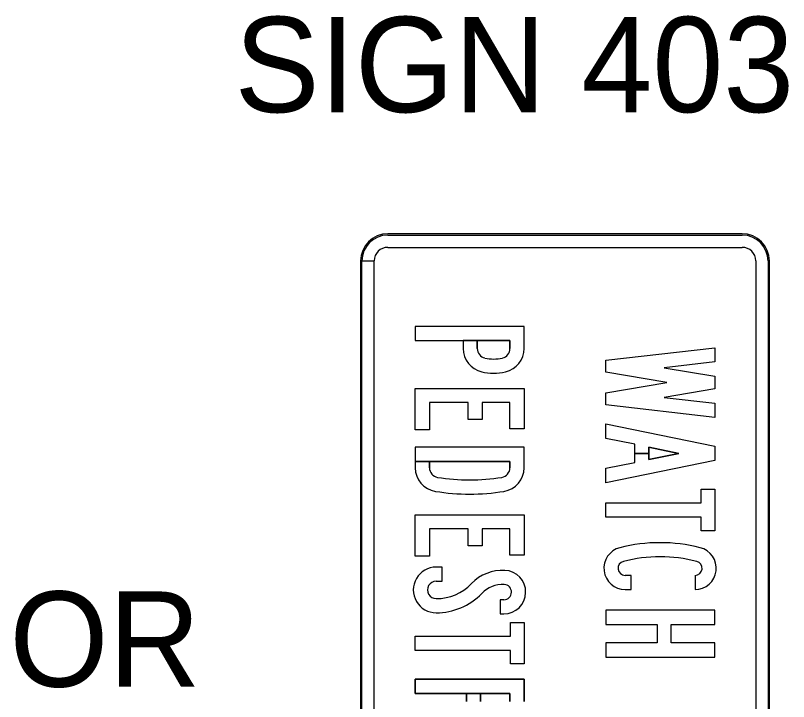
# Model space of a CAD drawing. Extents: x 524708 to 525491, y 1531861 to 1532506.
# Drawn here: x 525120.66 to 525149.05, y 1532113.89 to 1532139.08 of the extents above; entities that cross this region are included whole.
import ezdxf

# ---------------------------------------------------------------- set-up
doc = ezdxf.new("R2010")
doc.units = 0
for name, color, linetype in [('GSBWFill', 7, 'Continuous'), ('GSColorFill', 7, 'Continuous'), ('GSOutline', 7, 'Continuous'), ('TextLabel', 7, 'Continuous')]:
    doc.layers.add(name, color=color, linetype=linetype)

msp = doc.modelspace()

# ---------------------------------------------------------------- linework, layer by layer
at = {"layer": 'GSBWFill'}
for p, q in [((525137.099, 1532127.145), (525137.099, 1532126.853)), ((525143.269, 1532118.52), (525143.049, 1532118.52)), ((525145.615, 1532118.52), (525145.615, 1532118)), ((525137.219, 1532113.886), (525137.219, 1532114.185))]:
    msp.add_line(p, q, dxfattribs=at)
for points in [[(525139.339, 1532126.853), (525139.339, 1532127.665), (525135.339, 1532127.665), (525135.339, 1532127.145), (525138.819, 1532127.145), (525138.819, 1532126.853)], [(525137.619, 1532126.853), (525137.619, 1532127.145), (525137.099, 1532127.145)], [(525139.339, 1532122.474), (525139.339, 1532123.225), (525135.339, 1532123.225), (525135.339, 1532122.705), (525138.819, 1532122.705), (525138.819, 1532122.474)], [(525135.859, 1532122.474), (525135.859, 1532122.705), (525135.339, 1532122.705), (525135.339, 1532122.474)], [(525136.109, 1532118.305), (525136.329, 1532118.305), (525136.329, 1532118.825), (525136.109, 1532118.825)], [(525143.049, 1532118), (525143.269, 1532118), (525143.269, 1532118.52)], [(525138.595, 1532117.625), (525138.455, 1532117.625), (525138.455, 1532117.105), (525138.595, 1532117.105)], [(525138.819, 1532113.886), (525138.819, 1532114.185), (525135.339, 1532114.185), (525135.339, 1532114.705), (525139.339, 1532114.705), (525139.339, 1532113.886)], [(525137.219, 1532114.185), (525137.739, 1532114.185), (525137.739, 1532113.886)]]:
    msp.add_lwpolyline(points, dxfattribs=at)
for points in [[(525144.579, 1532125.6), (525142.339, 1532125.98), (525142.339, 1532126.42), (525146.339, 1532126.88), (525146.339, 1532126.357), (525144.485, 1532126.144), (525146.339, 1532125.829), (525146.339, 1532125.371), (525144.485, 1532125.057), (525146.339, 1532124.844), (525146.339, 1532124.32), (525142.339, 1532124.78), (525142.339, 1532125.22)], [(525139.339, 1532123.905), (525138.819, 1532123.905), (525138.819, 1532124.865), (525137.799, 1532124.865), (525137.799, 1532124.245), (525137.279, 1532124.245), (525137.279, 1532124.865), (525135.859, 1532124.865), (525135.859, 1532123.865), (525135.339, 1532123.865), (525135.339, 1532125.385), (525139.339, 1532125.385)], [(525143.919, 1532123), (525143.919, 1532122.775), (525145.018, 1532123), (525143.919, 1532123.226), (525143.919, 1532123), (525143.399, 1532123), (525143.399, 1532123.332), (525142.339, 1532123.549), (525142.339, 1532124.08), (525146.339, 1532123.26), (525146.339, 1532122.74), (525142.339, 1532121.92), (525142.339, 1532122.451), (525143.399, 1532122.668), (525143.399, 1532123)], [(525145.839, 1532120.16), (525145.839, 1532120.66), (525142.339, 1532120.66), (525142.339, 1532121.18), (525145.839, 1532121.18), (525145.839, 1532121.68), (525146.339, 1532121.68), (525146.339, 1532120.16)], [(525139.339, 1532119.265), (525138.819, 1532119.265), (525138.819, 1532120.225), (525137.799, 1532120.225), (525137.799, 1532119.605), (525137.279, 1532119.605), (525137.279, 1532120.225), (525135.859, 1532120.225), (525135.859, 1532119.225), (525135.339, 1532119.225), (525135.339, 1532120.745), (525139.339, 1532120.745)], [(525142.339, 1532117.24), (525142.339, 1532116.72), (525144.219, 1532116.72), (525144.219, 1532116.04), (525142.339, 1532116.04), (525142.339, 1532115.52), (525146.339, 1532115.52), (525146.339, 1532116.04), (525144.739, 1532116.04), (525144.739, 1532116.72), (525146.339, 1532116.72), (525146.339, 1532117.24)], [(525138.839, 1532115.265), (525138.839, 1532115.765), (525135.339, 1532115.765), (525135.339, 1532116.285), (525138.839, 1532116.285), (525138.839, 1532116.785), (525139.339, 1532116.785), (525139.339, 1532115.265)]]:
    msp.add_lwpolyline(points, close=True, dxfattribs=at)
for centre, radius, start, end in [((525137.979, 1532126.853), 0.88, 180, 256.9139), ((525137.979, 1532126.853), 0.36, 180, 256.9139), ((525138.459, 1532126.853), 0.36, 283.0861, 0), ((525138.459, 1532126.853), 0.88, 283.0861, 0), ((525138.219, 1532127.885), 1.42, 256.9139, 283.0861), ((525138.219, 1532127.885), 1.94, 256.9139, 283.0861)]:
    msp.add_arc(centre, radius, start, end, dxfattribs=at)
for centre, major_axis, ratio, start_param, end_param in [((525136.219, 1532122.474), (0.88, 0), 0.999988, 3.141593, 4.55443), ((525136.219, 1532122.474), (0.36, 0), 0.999988, 3.141593, 4.55443), ((525138.459, 1532122.474), (0.36, 0), 0.999988, 4.870348, 6.283185), ((525138.459, 1532122.474), (0.88, 0), 0.999988, 4.870348, 6.283185), ((525137.339, 1532129.505), (7.48, 0), 0.999988, 4.55443, 4.870348), ((525137.339, 1532129.505), (8, 0), 0.999988, 4.55443, 4.870348), ((525144.332, 1532113.716), (6.004, 0), 0.999996, 1.322662, 1.818931), ((525143.049, 1532118.78), (0.78, 0), 0.999996, 1.818931, 4.712389), ((525145.615, 1532118.78), (0.78, 0), 0.999996, 4.712389, 7.605847), ((525143.049, 1532118.78), (0.26, 0), 0.999996, 1.818931, 4.712389), ((525144.332, 1532113.716), (5.484, 0), 0.999996, 1.322662, 1.818931), ((525145.615, 1532118.78), (0.26, 0), 0.999996, 4.712389, 7.605847), ((525136.109, 1532117.985), (0.84, 0), 0.999996, 1.570796, 4.712389), ((525138.558, 1532117.106), (1.6, 0), 0.999996, 1.523757, 2.374761), ((525138.595, 1532117.905), (0.8, 0), 0.999996, 4.712389, 7.806942), ((525136.109, 1532117.985), (0.32, 0), 0.999996, 1.570796, 4.712389), ((525136.109, 1532119.465), (1.8, 0), 0.999996, 4.712389, 5.516353), ((525138.558, 1532117.106), (1.08, 0), 0.999996, 1.523757, 2.374761), ((525138.595, 1532117.905), (0.28, 0), 0.999996, 4.712389, 7.806942), ((525136.109, 1532119.465), (2.32, 0), 0.999996, 4.712389, 5.516353)]:
    msp.add_ellipse(centre, major_axis=major_axis, ratio=ratio, start_param=start_param, end_param=end_param, dxfattribs=at)
at = {"layer": 'GSColorFill'}
for p, q in [((525147.345, 1532131.066), (525134.333, 1532131.066)), ((525147.345, 1532131.066), (525134.333, 1532131.066)), ((525147.345, 1532131.066), (525134.333, 1532131.066)), ((525134.333, 1532131.016), (525147.345, 1532131.016)), ((525134.333, 1532130.566), (525147.345, 1532130.566)), ((525133.333, 1532130.066), (525133.833, 1532130.066)), ((525133.333, 1532130.066), (525133.333, 1532102.054)), ((525133.333, 1532130.066), (525133.383, 1532130.066)), ((525133.383, 1532130.066), (525133.333, 1532130.066)), ((525133.333, 1532130.066), (525133.333, 1532102.054)), ((525133.333, 1532130.061), (525133.333, 1532102.054)), ((525133.833, 1532130.061), (525133.333, 1532130.061)), ((525133.383, 1532102.054), (525133.383, 1532130.066)), ((525133.833, 1532102.054), (525133.833, 1532130.061)), ((525147.845, 1532130.066), (525147.845, 1532102.054)), ((525148.295, 1532130.066), (525148.295, 1532102.054)), ((525148.345, 1532102.054), (525148.345, 1532130.066)), ((525148.345, 1532102.054), (525148.345, 1532130.066)), ((525148.345, 1532102.054), (525148.345, 1532130.066)), ((525137.099, 1532127.145), (525137.099, 1532126.853)), ((525143.269, 1532118.52), (525143.049, 1532118.52)), ((525145.615, 1532118.52), (525145.615, 1532118)), ((525137.219, 1532113.886), (525137.219, 1532114.185))]:
    msp.add_line(p, q, dxfattribs=at)
for points in [[(525139.339, 1532126.853), (525139.339, 1532127.665), (525135.339, 1532127.665), (525135.339, 1532127.145), (525138.819, 1532127.145), (525138.819, 1532126.853)], [(525137.619, 1532126.853), (525137.619, 1532127.145), (525137.099, 1532127.145)], [(525139.339, 1532122.474), (525139.339, 1532123.225), (525135.339, 1532123.225), (525135.339, 1532122.705), (525138.819, 1532122.705), (525138.819, 1532122.474)], [(525135.859, 1532122.474), (525135.859, 1532122.705), (525135.339, 1532122.705), (525135.339, 1532122.474)], [(525136.109, 1532118.305), (525136.329, 1532118.305), (525136.329, 1532118.825), (525136.109, 1532118.825)], [(525143.049, 1532118), (525143.269, 1532118), (525143.269, 1532118.52)], [(525138.595, 1532117.625), (525138.455, 1532117.625), (525138.455, 1532117.105), (525138.595, 1532117.105)], [(525138.819, 1532113.886), (525138.819, 1532114.185), (525135.339, 1532114.185), (525135.339, 1532114.705), (525139.339, 1532114.705), (525139.339, 1532113.886)], [(525137.219, 1532114.185), (525137.739, 1532114.185), (525137.739, 1532113.886)]]:
    msp.add_lwpolyline(points, dxfattribs=at)
for points in [[(525144.579, 1532125.6), (525142.339, 1532125.98), (525142.339, 1532126.42), (525146.339, 1532126.88), (525146.339, 1532126.357), (525144.485, 1532126.144), (525146.339, 1532125.829), (525146.339, 1532125.371), (525144.485, 1532125.057), (525146.339, 1532124.844), (525146.339, 1532124.32), (525142.339, 1532124.78), (525142.339, 1532125.22)], [(525139.339, 1532123.905), (525138.819, 1532123.905), (525138.819, 1532124.865), (525137.799, 1532124.865), (525137.799, 1532124.245), (525137.279, 1532124.245), (525137.279, 1532124.865), (525135.859, 1532124.865), (525135.859, 1532123.865), (525135.339, 1532123.865), (525135.339, 1532125.385), (525139.339, 1532125.385)], [(525143.919, 1532123), (525143.919, 1532122.775), (525145.018, 1532123), (525143.919, 1532123.226), (525143.919, 1532123), (525143.399, 1532123), (525143.399, 1532123.332), (525142.339, 1532123.549), (525142.339, 1532124.08), (525146.339, 1532123.26), (525146.339, 1532122.74), (525142.339, 1532121.92), (525142.339, 1532122.451), (525143.399, 1532122.668), (525143.399, 1532123)], [(525145.839, 1532120.16), (525145.839, 1532120.66), (525142.339, 1532120.66), (525142.339, 1532121.18), (525145.839, 1532121.18), (525145.839, 1532121.68), (525146.339, 1532121.68), (525146.339, 1532120.16)], [(525139.339, 1532119.265), (525138.819, 1532119.265), (525138.819, 1532120.225), (525137.799, 1532120.225), (525137.799, 1532119.605), (525137.279, 1532119.605), (525137.279, 1532120.225), (525135.859, 1532120.225), (525135.859, 1532119.225), (525135.339, 1532119.225), (525135.339, 1532120.745), (525139.339, 1532120.745)], [(525142.339, 1532117.24), (525142.339, 1532116.72), (525144.219, 1532116.72), (525144.219, 1532116.04), (525142.339, 1532116.04), (525142.339, 1532115.52), (525146.339, 1532115.52), (525146.339, 1532116.04), (525144.739, 1532116.04), (525144.739, 1532116.72), (525146.339, 1532116.72), (525146.339, 1532117.24)], [(525138.839, 1532115.265), (525138.839, 1532115.765), (525135.339, 1532115.765), (525135.339, 1532116.285), (525138.839, 1532116.285), (525138.839, 1532116.785), (525139.339, 1532116.785), (525139.339, 1532115.265)]]:
    msp.add_lwpolyline(points, close=True, dxfattribs=at)
for centre, radius, start, end in [((525134.333, 1532130.066), 1, 90, 180), ((525134.333, 1532130.066), 1, 90, 180), ((525134.333, 1532130.066), 1, 90, 180), ((525134.333, 1532130.066), 0.95, 90, 180), ((525147.345, 1532130.066), 1, 0, 90), ((525147.345, 1532130.066), 1, 0, 90), ((525147.345, 1532130.066), 1, 0, 90), ((525147.345, 1532130.066), 0.95, 0, 90), ((525134.333, 1532130.066), 0.5, 90, 180), ((525147.345, 1532130.066), 0.5, 0, 90), ((525137.979, 1532126.853), 0.88, 180, 256.9139), ((525137.979, 1532126.853), 0.36, 180, 256.9139), ((525138.459, 1532126.853), 0.36, 283.0861, 0), ((525138.459, 1532126.853), 0.88, 283.0861, 0), ((525138.219, 1532127.885), 1.42, 256.9139, 283.0861), ((525138.219, 1532127.885), 1.94, 256.9139, 283.0861)]:
    msp.add_arc(centre, radius, start, end, dxfattribs=at)
for centre, major_axis, ratio, start_param, end_param in [((525136.219, 1532122.474), (0.88, 0), 0.999988, 3.141593, 4.55443), ((525136.219, 1532122.474), (0.36, 0), 0.999988, 3.141593, 4.55443), ((525138.459, 1532122.474), (0.36, 0), 0.999988, 4.870348, 6.283185), ((525138.459, 1532122.474), (0.88, 0), 0.999988, 4.870348, 6.283185), ((525137.339, 1532129.505), (7.48, 0), 0.999988, 4.55443, 4.870348), ((525137.339, 1532129.505), (8, 0), 0.999988, 4.55443, 4.870348), ((525144.332, 1532113.716), (6.004, 0), 0.999996, 1.322662, 1.818931), ((525143.049, 1532118.78), (0.78, 0), 0.999996, 1.818931, 4.712389), ((525145.615, 1532118.78), (0.78, 0), 0.999996, 4.712389, 7.605847), ((525143.049, 1532118.78), (0.26, 0), 0.999996, 1.818931, 4.712389), ((525144.332, 1532113.716), (5.484, 0), 0.999996, 1.322662, 1.818931), ((525145.615, 1532118.78), (0.26, 0), 0.999996, 4.712389, 7.605847), ((525136.109, 1532117.985), (0.84, 0), 0.999996, 1.570796, 4.712389), ((525138.558, 1532117.106), (1.6, 0), 0.999996, 1.523757, 2.374761), ((525138.595, 1532117.905), (0.8, 0), 0.999996, 4.712389, 7.806942), ((525136.109, 1532117.985), (0.32, 0), 0.999996, 1.570796, 4.712389), ((525136.109, 1532119.465), (1.8, 0), 0.999996, 4.712389, 5.516353), ((525138.558, 1532117.106), (1.08, 0), 0.999996, 1.523757, 2.374761), ((525138.595, 1532117.905), (0.28, 0), 0.999996, 4.712389, 7.806942), ((525136.109, 1532119.465), (2.32, 0), 0.999996, 4.712389, 5.516353)]:
    msp.add_ellipse(centre, major_axis=major_axis, ratio=ratio, start_param=start_param, end_param=end_param, dxfattribs=at)
at = {"layer": 'GSOutline'}
for p, q in [((525138.819, 1532126.853), (525138.819, 1532127.145)), ((525135.859, 1532122.705), (525135.859, 1532122.474)), ((525143.269, 1532118.52), (525143.049, 1532118.52)), ((525145.615, 1532118.52), (525145.615, 1532118)), ((525137.219, 1532114.185), (525137.219, 1532113.886))]:
    msp.add_line(p, q, dxfattribs=at)
for points in [[(525139.339, 1532126.853), (525139.339, 1532127.665), (525135.339, 1532127.665), (525135.339, 1532127.145)], [(525135.339, 1532127.145), (525137.099, 1532127.145), (525137.099, 1532126.853)], [(525138.819, 1532127.145), (525137.619, 1532127.145), (525137.619, 1532126.853)], [(525139.339, 1532122.474), (525139.339, 1532123.225), (525135.339, 1532123.225), (525135.339, 1532122.474)], [(525138.819, 1532122.474), (525138.819, 1532122.705), (525135.859, 1532122.705)], [(525136.109, 1532118.305), (525136.329, 1532118.305), (525136.329, 1532118.825), (525136.109, 1532118.825)], [(525143.049, 1532118), (525143.269, 1532118), (525143.269, 1532118.52)], [(525138.595, 1532117.625), (525138.455, 1532117.625), (525138.455, 1532117.105), (525138.595, 1532117.105)], [(525139.339, 1532113.886), (525139.339, 1532114.705), (525135.339, 1532114.705), (525135.339, 1532114.185), (525137.219, 1532114.185)], [(525137.739, 1532113.886), (525137.739, 1532114.185), (525138.819, 1532114.185), (525138.819, 1532113.886)]]:
    msp.add_lwpolyline(points, dxfattribs=at)
for points in [[(525144.579, 1532125.6), (525142.339, 1532125.98), (525142.339, 1532126.42), (525146.339, 1532126.88), (525146.339, 1532126.357), (525144.485, 1532126.144), (525146.339, 1532125.829), (525146.339, 1532125.371), (525144.485, 1532125.057), (525146.339, 1532124.844), (525146.339, 1532124.32), (525142.339, 1532124.78), (525142.339, 1532125.22)], [(525139.339, 1532123.905), (525138.819, 1532123.905), (525138.819, 1532124.865), (525137.799, 1532124.865), (525137.799, 1532124.245), (525137.279, 1532124.245), (525137.279, 1532124.865), (525135.859, 1532124.865), (525135.859, 1532123.865), (525135.339, 1532123.865), (525135.339, 1532125.385), (525139.339, 1532125.385)], [(525142.339, 1532123.549), (525142.339, 1532124.08), (525146.339, 1532123.26), (525146.339, 1532122.74), (525142.339, 1532121.92), (525142.339, 1532122.451), (525143.399, 1532122.668), (525143.399, 1532123.332)], [(525143.919, 1532122.775), (525143.919, 1532123.226), (525145.018, 1532123)], [(525145.839, 1532120.16), (525145.839, 1532120.66), (525142.339, 1532120.66), (525142.339, 1532121.18), (525145.839, 1532121.18), (525145.839, 1532121.68), (525146.339, 1532121.68), (525146.339, 1532120.16)], [(525139.339, 1532119.265), (525138.819, 1532119.265), (525138.819, 1532120.225), (525137.799, 1532120.225), (525137.799, 1532119.605), (525137.279, 1532119.605), (525137.279, 1532120.225), (525135.859, 1532120.225), (525135.859, 1532119.225), (525135.339, 1532119.225), (525135.339, 1532120.745), (525139.339, 1532120.745)], [(525142.339, 1532117.24), (525142.339, 1532116.72), (525144.219, 1532116.72), (525144.219, 1532116.04), (525142.339, 1532116.04), (525142.339, 1532115.52), (525146.339, 1532115.52), (525146.339, 1532116.04), (525144.739, 1532116.04), (525144.739, 1532116.72), (525146.339, 1532116.72), (525146.339, 1532117.24)], [(525138.839, 1532115.265), (525138.839, 1532115.765), (525135.339, 1532115.765), (525135.339, 1532116.285), (525138.839, 1532116.285), (525138.839, 1532116.785), (525139.339, 1532116.785), (525139.339, 1532115.265)]]:
    msp.add_lwpolyline(points, close=True, dxfattribs=at)
for centre, radius, start, end in [((525137.979, 1532126.853), 0.88, 180, 256.9139), ((525137.979, 1532126.853), 0.36, 180, 256.9139), ((525138.459, 1532126.853), 0.36, 283.0861, 0), ((525138.459, 1532126.853), 0.88, 283.0861, 0), ((525138.219, 1532127.885), 1.42, 256.9139, 283.0861), ((525138.219, 1532127.885), 1.94, 256.9139, 283.0861)]:
    msp.add_arc(centre, radius, start, end, dxfattribs=at)
for centre, major_axis, ratio, start_param, end_param in [((525136.219, 1532122.474), (0.88, 0), 0.999988, 3.141593, 4.55443), ((525136.219, 1532122.474), (0.36, 0), 0.999988, 3.141593, 4.55443), ((525138.459, 1532122.474), (0.36, 0), 0.999988, 4.870348, 6.283185), ((525138.459, 1532122.474), (0.88, 0), 0.999988, 4.870348, 6.283185), ((525137.339, 1532129.505), (7.48, 0), 0.999988, 4.55443, 4.870348), ((525137.339, 1532129.505), (8, 0), 0.999988, 4.55443, 4.870348), ((525144.332, 1532113.716), (6.004, 0), 0.999996, 1.322662, 1.818931), ((525143.049, 1532118.78), (0.78, 0), 0.999996, 1.818931, 4.712389), ((525145.615, 1532118.78), (0.78, 0), 0.999996, 4.712389, 7.605847), ((525143.049, 1532118.78), (0.26, 0), 0.999996, 1.818931, 4.712389), ((525144.332, 1532113.716), (5.484, 0), 0.999996, 1.322662, 1.818931), ((525145.615, 1532118.78), (0.26, 0), 0.999996, 4.712389, 7.605847), ((525136.109, 1532117.985), (0.84, 0), 0.999996, 1.570796, 4.712389), ((525138.558, 1532117.106), (1.6, 0), 0.999996, 1.523757, 2.374761), ((525138.595, 1532117.905), (0.8, 0), 0.999996, 4.712389, 7.806942), ((525136.109, 1532117.985), (0.32, 0), 0.999996, 1.570796, 4.712389), ((525136.109, 1532119.465), (1.8, 0), 0.999996, 4.712389, 5.516353), ((525138.558, 1532117.106), (1.08, 0), 0.999996, 1.523757, 2.374761), ((525138.595, 1532117.905), (0.28, 0), 0.999996, 4.712389, 7.806942), ((525136.109, 1532119.465), (2.32, 0), 0.999996, 4.712389, 5.516353)]:
    msp.add_ellipse(centre, major_axis=major_axis, ratio=ratio, start_param=start_param, end_param=end_param, dxfattribs=at)

# ---------------------------------------------------------------- texts
at = {"layer": 'TextLabel'}
for s, p in [('SIGN 403', (525128.703, 1532135.53)), ('OR', (525120.436, 1532114.429))]:
    msp.add_text(s, height=3.5, dxfattribs=at).set_placement(p)

doc.saveas('drawing.dxf')
